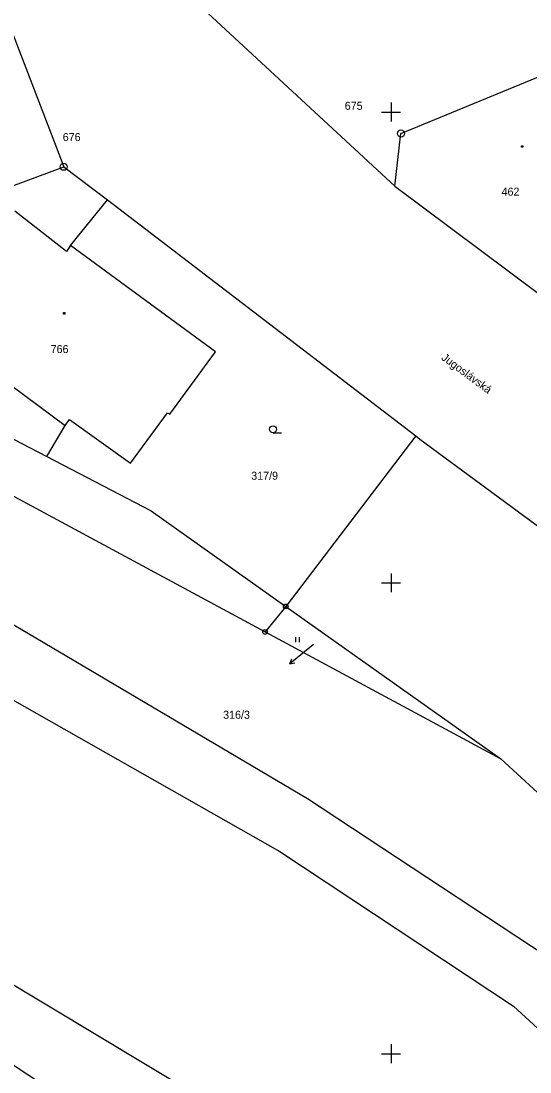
# Model space of a CAD drawing. Extents: x -492379 to -491966, y -1126153 to -1125860.
# Drawn here: x -492233.6 to -492201.2, y -1125961.2 to -1125894.2 of the extents above; entities that cross this region are included whole.
import ezdxf

# ---------------------------------------------------------------- set-up
doc = ezdxf.new("R2010")
doc.units = 0
doc.layers.add('katastrální mapa', color=7, linetype='Continuous')
doc.layers.add('síť', color=7, linetype='Continuous')

msp = doc.modelspace()

# ---------------------------------------------------------------- linework, layer by layer
at = {"layer": 'katastrální mapa'}
for p, q in [((-492235.22, -1125892.14), (-492230.86, -1125903.49)), ((-492221.68, -1125893.7), (-492209.77, -1125904.73)), ((-492209.37, -1125901.37), (-492198.3, -1125896.79)), ((-492209.77, -1125904.73), (-492209.37, -1125901.37)), ((-492201.69, -1125902.15), (-492201.6, -1125902.15)), ((-492201.69, -1125902.24), (-492201.69, -1125902.15)), ((-492201.6, -1125902.24), (-492201.69, -1125902.24)), ((-492201.6, -1125902.15), (-492201.6, -1125902.24)), ((-492241.03, -1125907.27), (-492230.86, -1125903.49)), ((-492230.86, -1125903.49), (-492228.06, -1125905.59)), ((-492209.77, -1125904.73), (-492200.7, -1125911.49)), ((-492230.42, -1125908.5), (-492228.06, -1125905.59)), ((-492228.06, -1125905.59), (-492208.43, -1125920.64)), ((-492230.69, -1125908.88), (-492233.98, -1125906.31)), ((-492230.42, -1125908.5), (-492230.69, -1125908.88)), ((-492221.19, -1125915.28), (-492230.42, -1125908.5)), ((-492230.88, -1125912.78), (-492230.79, -1125912.78)), ((-492230.88, -1125912.87), (-492230.88, -1125912.78)), ((-492230.79, -1125912.78), (-492230.79, -1125912.87)), ((-492230.79, -1125912.87), (-492230.88, -1125912.87)), ((-492224.1, -1125919.26), (-492221.19, -1125915.28)), ((-492235.45, -1125916.49), (-492230.77, -1125919.97)), ((-492248.04, -1125916.95), (-492218.03, -1125933.13)), ((-492239.27, -1125918.13), (-492231.94, -1125921.95)), ((-492258.01, -1125918.53), (-492215.33, -1125943.73)), ((-492226.6, -1125922.37), (-492224.24, -1125919.17)), ((-492224.24, -1125919.17), (-492224.1, -1125919.26)), ((-492231.94, -1125921.95), (-492230.77, -1125919.97)), ((-492230.77, -1125919.97), (-492230.49, -1125919.59)), ((-492230.49, -1125919.59), (-492226.6, -1125922.37)), ((-492217.52, -1125920.44), (-492216.99, -1125920.44)), ((-492208.43, -1125920.64), (-492216.71, -1125931.5)), ((-492208.43, -1125920.64), (-492208.16, -1125920.85)), ((-492208.16, -1125920.85), (-492176.98, -1125943.81)), ((-492231.94, -1125921.95), (-492225.28, -1125925.42)), ((-492260.24, -1125922.63), (-492217.08, -1125947.12)), ((-492225.28, -1125925.42), (-492216.71, -1125931.5)), ((-492216.71, -1125931.5), (-492218.03, -1125933.13)), ((-492216.71, -1125931.5), (-492203.01, -1125941.22)), ((-492218.03, -1125933.13), (-492203.01, -1125941.22)), ((-492216.06, -1125933.77), (-492216.06, -1125933.47)), ((-492215.86, -1125933.47), (-492215.86, -1125933.77)), ((-492214.95, -1125933.93), (-492215.76, -1125934.59)), ((-492215.76, -1125934.59), (-492216.46, -1125935.16)), ((-492216.46, -1125935.16), (-492216.32, -1125934.85)), ((-492216.46, -1125935.16), (-492216.13, -1125935.09)), ((-492203.01, -1125941.22), (-492188.24, -1125954.78)), ((-492215.33, -1125943.73), (-492200.12, -1125953.76)), ((-492217.08, -1125947.12), (-492202.19, -1125956.98)), ((-492237.9, -1125953.3), (-492214.61, -1125967.28)), ((-492239.95, -1125956.88), (-492218.05, -1125971.18)), ((-492202.19, -1125956.98), (-492186.86, -1125971.15))]:
    msp.add_line(p, q, dxfattribs=at)
for centre, radius in [((-492209.37, -1125901.37), 0.225), ((-492209.37, -1125901.37), 0.003), ((-492230.86, -1125903.49), 0.225), ((-492230.86, -1125903.49), 0.003), ((-492217.52, -1125920.215), 0.225), ((-492216.71, -1125931.5), 0.15), ((-492216.71, -1125931.5), 0.003), ((-492218.03, -1125933.13), 0.15), ((-492218.03, -1125933.13), 0.003)]:
    msp.add_circle(centre, radius, dxfattribs=at)
at = {"layer": 'síť'}
for p, q in [((-492210, -1125899.4), (-492210, -1125900.6)), ((-492210.6, -1125900), (-492209.4, -1125900)), ((-492210, -1125929.4), (-492210, -1125930.6)), ((-492210.6, -1125930), (-492209.4, -1125930)), ((-492210, -1125959.4), (-492210, -1125960.6)), ((-492210.6, -1125960), (-492209.4, -1125960))]:
    msp.add_line(p, q, dxfattribs=at)

# ---------------------------------------------------------------- texts
at = {"layer": 'katastrální mapa'}
for s, height, p in [('675', 0.51, (-492212.95, -1125899.86)), ('676', 0.51, (-492230.92, -1125901.85)), ('462', 0.51, (-492202.96, -1125905.33)), ('766', 0.51, (-492231.69, -1125915.36)), ('317/9', 0.51, (-492218.91, -1125923.43)), ('316/3', 0.03, (-492215.01, -1125933.93)), ('316/3', 0.51, (-492220.7, -1125938.66))]:
    msp.add_text(s, height=height, dxfattribs=at).set_placement(p)
msp.add_text('Jugoslávská', height=0.50999, rotation=323.496, dxfattribs=at).set_placement((-492206.84, -1125915.74))

doc.saveas('drawing.dxf')
